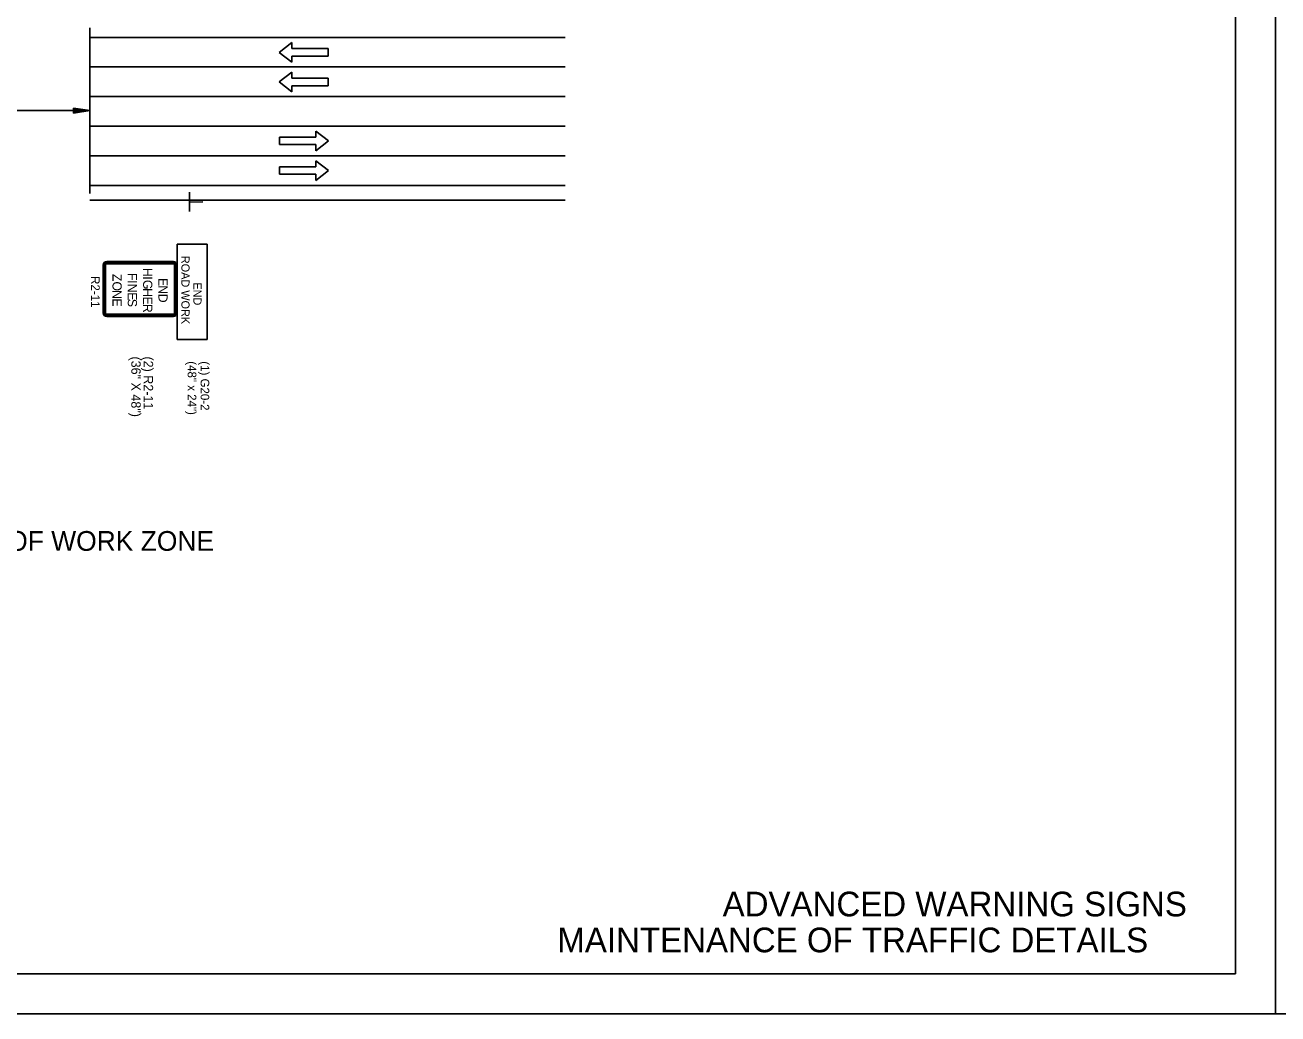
# Model space of a CAD drawing. Extents: x 32485 to 39285, y 55121 to 58033.
# Drawn here: x 35108 to 35886, y 56764 to 57379 of the extents above; entities that cross this region are included whole.
import ezdxf

# ---------------------------------------------------------------- set-up
doc = ezdxf.new("R2010")
doc.units = 0
for name, color, linetype in [('Default', 7, 'Continuous'), ('R_Border', 7, 'Continuous'), ('R_Border Notes', 7, 'Continuous'), ('R_Draft', 7, 'Continuous'), ('R_Exist Surface', 7, 'Continuous'), ('R_MOT', 7, 'Continuous')]:
    doc.layers.add(name, color=color, linetype=linetype)

msp = doc.modelspace()

# ---------------------------------------------------------------- linework, layer by layer
at = {"layer": 'Default'}
for p, q in [((35148.06, 57273.93), (35148.06, 57376.82)), ((35265.64, 57361.6), (35273.6, 57367.74)), ((35273.6, 57363.9), (35273.6, 57367.74)), ((35273.6, 57355.46), (35265.64, 57361.6)), ((35273.6, 57363.9), (35296.17, 57363.9)), ((35296.17, 57359.3), (35296.17, 57363.9)), ((35273.6, 57359.3), (35296.17, 57359.3)), ((35273.6, 57355.46), (35273.6, 57359.3)), ((35265.64, 57343.19), (35273.6, 57349.33)), ((35273.6, 57345.49), (35273.6, 57349.33)), ((35273.6, 57345.49), (35296.17, 57345.49)), ((35296.17, 57340.89), (35296.17, 57345.49)), ((35273.6, 57337.05), (35265.64, 57343.19)), ((35273.6, 57340.89), (35296.17, 57340.89)), ((35273.6, 57337.05), (35273.6, 57340.89)), ((34884.44, 57325.37), (35148.06, 57325.37)), ((35288.37, 57308.83), (35265.8, 57308.83)), ((35265.8, 57308.83), (35265.8, 57304.23)), ((35288.37, 57312.67), (35288.37, 57308.83)), ((35288.37, 57312.67), (35296.34, 57306.53)), ((35296.34, 57306.53), (35288.37, 57300.4)), ((35288.37, 57304.23), (35265.8, 57304.23)), ((35288.37, 57304.23), (35288.37, 57300.4)), ((35288.37, 57290.42), (35265.8, 57290.42)), ((35265.8, 57290.42), (35265.8, 57285.82)), ((35288.37, 57294.26), (35288.37, 57290.42)), ((35288.37, 57294.26), (35296.34, 57288.12)), ((35288.37, 57285.82), (35265.8, 57285.82)), ((35296.34, 57288.12), (35288.37, 57281.99)), ((35288.37, 57285.82), (35288.37, 57281.99)), ((35156.36, 57229.5), (35156.36, 57199.52)), ((35156.96, 57229.5), (35156.96, 57199.52)), ((35157.79, 57199.52), (35157.79, 57229.5)), ((35199.91, 57231.64), (35158.5, 57231.64)), ((35199.91, 57231.05), (35158.5, 57231.05)), ((35158.5, 57230.21), (35199.91, 57230.21)), ((35200.62, 57229.5), (35200.62, 57199.52)), ((35201.45, 57199.52), (35201.45, 57229.5)), ((35202.05, 57199.52), (35202.05, 57229.5)), ((35199.91, 57198.8), (35158.5, 57198.8)), ((35158.5, 57197.97), (35199.91, 57197.97)), ((35158.5, 57197.38), (35199.91, 57197.38))]:
    msp.add_line(p, q, dxfattribs=at)
for points in [[(34185, 57863.91), (34185, 56763.91), (35885, 56763.91), (35885, 57863.91)], [(35885, 57863.91), (35885, 56763.91), (37585, 56763.91), (37585, 57863.91)]]:
    msp.add_lwpolyline(points, close=True, dxfattribs=at)
for centre, radius, start, end in [((35158.5, 57229.5), 2.14, 90, 180.00001), ((35158.5, 57229.5), 1.55, 90.00001, 180), ((35158.5, 57229.5), 0.714, 90.00001, 180), ((35199.91, 57229.5), 2.14, 0, 90), ((35199.91, 57229.5), 1.55, 0, 90.00001), ((35199.91, 57229.5), 0.714, 0, 90.00001), ((35158.5, 57199.52), 2.14, 180.00001, 270.00001), ((35158.5, 57199.52), 1.55, 180, 270.00001), ((35158.5, 57199.52), 0.714, 180, 270.00001), ((35199.91, 57199.52), 2.14, 270, 0), ((35199.91, 57199.52), 1.55, 270, 0), ((35199.91, 57199.52), 0.714, 270, 0)]:
    msp.add_arc(centre, radius, start, end, dxfattribs=at)
at = {"layer": 'R_Border'}
for p, q in [((35209.91, 57262.59), (35209.85, 57274.64)), ((35210.05, 57268.59), (35218.28, 57268.62)), ((35202.27, 57183.04), (35202.27, 57242.3)), ((35202.27, 57242.3), (35220.88, 57242.3)), ((35220.88, 57183.04), (35220.88, 57242.3)), ((35202.27, 57183.04), (35220.88, 57183.04))]:
    msp.add_line(p, q, dxfattribs=at)
at = {"layer": 'R_Border Notes'}
for points in [[(34185, 56763.91), (35885, 56763.91), (35885, 57863.91), (34185, 57863.91)], [(35885, 56763.91), (37585, 56763.91), (37585, 57863.91), (35885, 57863.91)], [(34210, 56788.91), (35860, 56788.91), (35860, 57838.91), (34210, 57838.91)]]:
    msp.add_lwpolyline(points, close=True, dxfattribs=at)
at = {"layer": 'R_Draft'}
for p, q in [((35137.83, 57326.91), (35148.06, 57325.37)), ((35137.83, 57326.91), (35137.83, 57323.84)), ((35137.83, 57326.65), (35146.35, 57325.37)), ((35137.83, 57326.39), (35144.59, 57325.37)), ((35137.83, 57326.14), (35142.88, 57325.37)), ((35137.83, 57325.87), (35141.15, 57325.37)), ((35137.83, 57325.61), (35139.44, 57325.37)), ((35137.83, 57323.84), (35148.06, 57325.37)), ((35137.83, 57324.87), (35141.15, 57325.37)), ((35137.83, 57324.36), (35144.59, 57325.37)), ((35137.83, 57324.1), (35146.35, 57325.37)), ((35137.83, 57324.61), (35142.88, 57325.37)), ((35137.83, 57325.13), (35139.44, 57325.37))]:
    msp.add_line(p, q, dxfattribs=at)
at = {"layer": 'R_Exist Surface'}
for p, q in [((35148.06, 57370.94), (35443.42, 57370.94)), ((35148.06, 57352.53), (35443.42, 57352.53)), ((35148.06, 57334.12), (35443.42, 57334.12)), ((35148.06, 57315.71), (35443.42, 57315.71)), ((35148.06, 57297.3), (35443.42, 57297.3)), ((35148.06, 57278.89), (35443.42, 57278.89)), ((35148.06, 57269.69), (35443.42, 57269.69))]:
    msp.add_line(p, q, dxfattribs=at)

# ---------------------------------------------------------------- texts
at = {"layer": 'Default'}
for s, height, p in [('R2-11', 5.384, (35148.74, 57222.56)), ('Z', 5.71, (35162.07, 57223.94)), ('F', 5.71, (35171.59, 57224.48)), ('I', 5.71, (35171.59, 57220.08)), ('G', 5.71, (35181.11, 57220.19)), ('H', 5.71, (35181.11, 57227.62)), ('I', 5.71, (35181.11, 57222.37)), ('E', 5.71, (35190.63, 57221.34)), ('O', 5.71, (35162.07, 57219.19)), ('N', 5.71, (35162.07, 57213.88)), ('N', 5.71, (35171.59, 57217.79)), ('E', 5.71, (35171.59, 57212.53)), ('H', 5.71, (35181.11, 57215.05)), ('N', 5.71, (35190.63, 57216.82)), ('E', 5.71, (35162.07, 57208.62)), ('S', 5.71, (35171.59, 57208.42)), ('E', 5.71, (35181.11, 57209.79)), ('R', 5.71, (35181.11, 57205.28)), ('D', 5.71, (35190.63, 57211.56))]:
    msp.add_text(s, height=height, rotation=270, dxfattribs=at).set_placement(p)
msp.add_text('ADVANCE WARNING SIGNS AT BEGINNING AND END OF WORK ZONE ', height=12.2732, dxfattribs=at).set_placement((34672.6, 57051.78))
at = {"layer": 'R_Border'}
for s, height, p in [('ROAD WORK', 5.058, (35204.89, 57235.13)), ('END', 5.058, (35212.36, 57218.62)), ('(48" x 24")', 5.3523, (35208.82, 57169.59)), ('(1) G20-2', 5.353, (35216.85, 57169.59))]:
    msp.add_text(s, height=height, rotation=270, dxfattribs=at).set_placement(p)
at = {"layer": 'R_Draft'}
for s, height, p in [('(36" X 48")', 5.8301, (35173.76, 57172.58)), ('(2) R2-11', 5.83, (35181.49, 57172.58))]:
    msp.add_text(s, height=height, rotation=270, dxfattribs=at).set_placement(p)
at = {"layer": 'R_MOT'}
for s, p in [('ADVANCED WARNING SIGNS', (35541.3, 56824.56)), ('MAINTENANCE OF TRAFFIC DETAILS', (35438.57, 56802.23))]:
    msp.add_text(s, height=15.349, dxfattribs=at).set_placement(p)

doc.saveas('drawing.dxf')
